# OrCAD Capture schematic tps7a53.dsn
size A
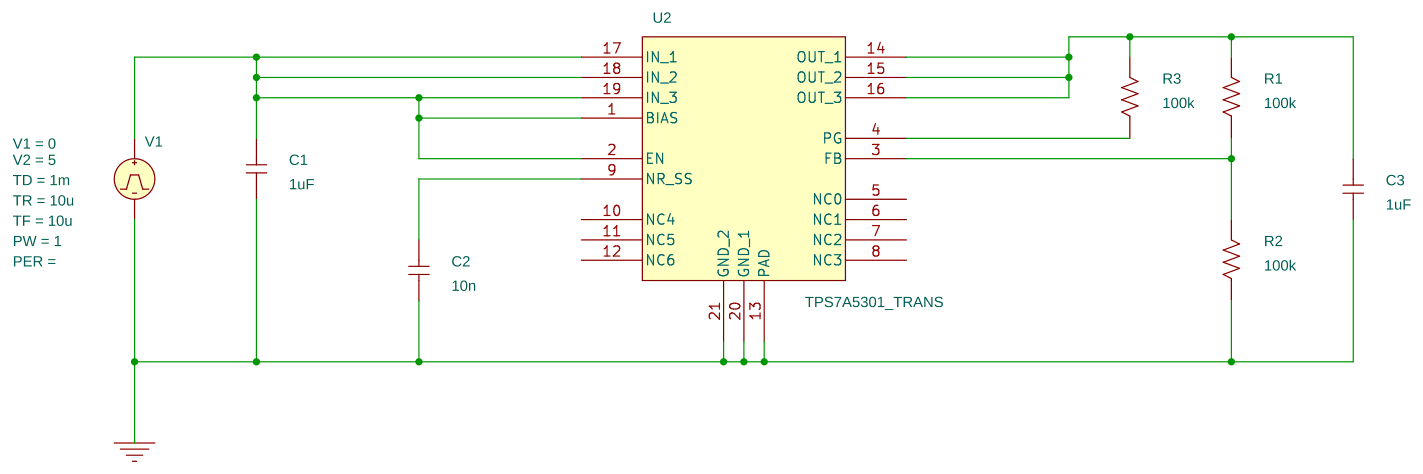
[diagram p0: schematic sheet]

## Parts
C1  1uF  [cap196]
C2  10n  [cap196]
C3  1uF  [cap196]
R1  100k  [AXRC05]
R2  100k  [AXRC05]
R3  100k  [AXRC05]
U2  TPS7A5301_TRANS
V1  VPULSE

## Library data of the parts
C1-C3 = C
R1-R3 = R
U2 = TPS7A5301_TRANS_1
V1 = VPULSE: PW: 1; TD: 1m; TF: 10u; TR: 10u; V1: 0; V2: 5

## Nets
0: C1.1 C2.1 C3.1 R2.1 U2.13(PAD) U2.20(GND_1) U2.21(GND_2) V1.2(-)
N00381: C1.2 U2.1(BIAS) U2.2(EN) U2.17(IN_1) U2.18(IN_2) U2.19(IN_3) V1.1(+)
N00720: C2.2 U2.9(NR_SS)
N00772: C3.2 R1.2 R3.2 U2.14(OUT_1) U2.15(OUT_2) U2.16(OUT_3)
N00920: R1.1 R2.2 U2.3(FB)
N01401: R3.1 U2.4(PG)

Not connected (* = marked no-connect by the designer): U2 5(NC0) 6(NC1) 7(NC2) 8(NC3) 10(NC4) 11(NC5) 12(NC6)
